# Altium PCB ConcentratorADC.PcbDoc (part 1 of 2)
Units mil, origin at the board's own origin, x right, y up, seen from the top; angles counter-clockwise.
Board outline 14400 x 5650 mil, 4 copper layers (Top Layer, Signal Layer 1, SG, Bottom Layer), stack 25.634 mil thick; 37 components, 129 nets, 1038 pads, 192 vias.
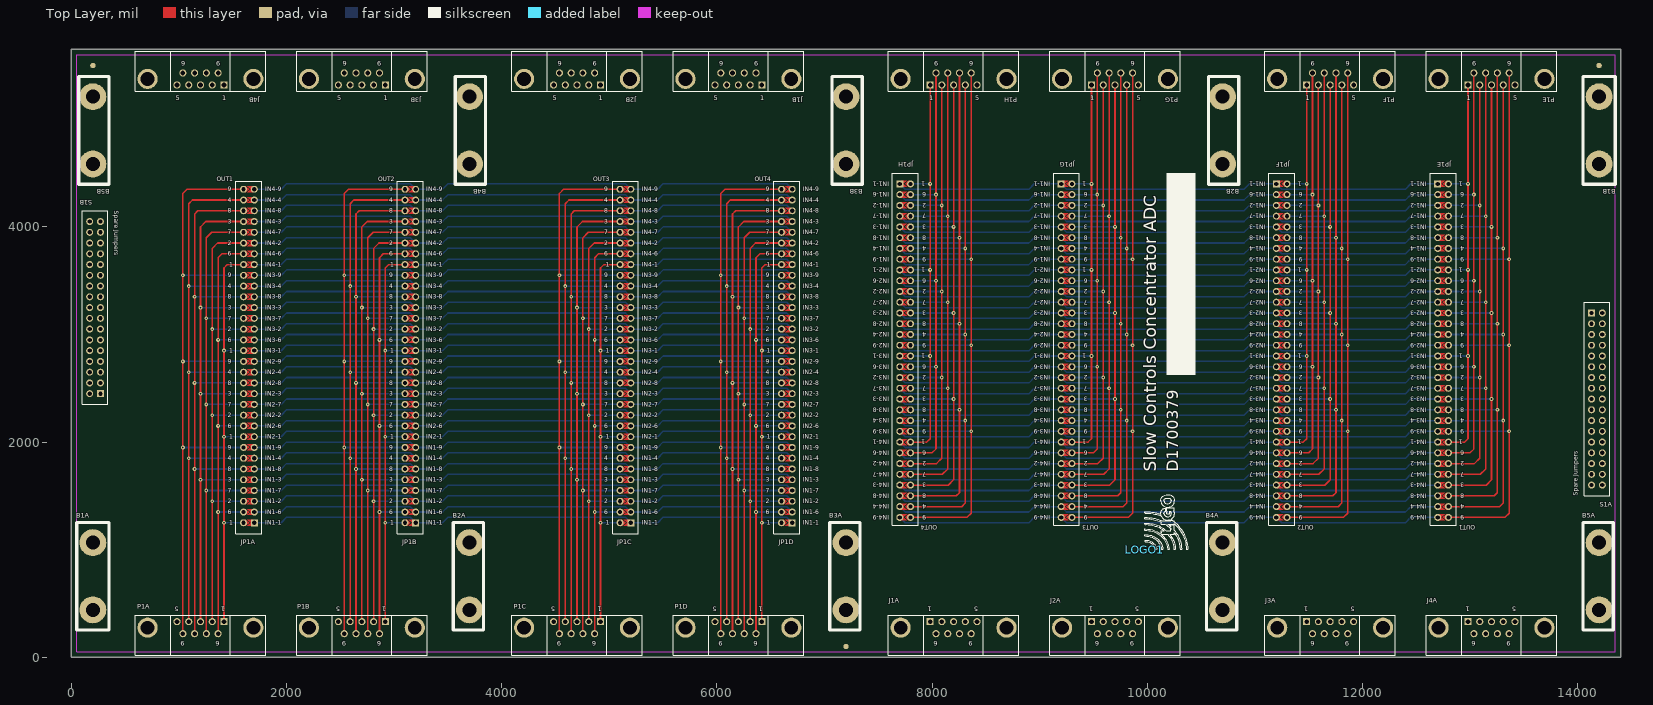
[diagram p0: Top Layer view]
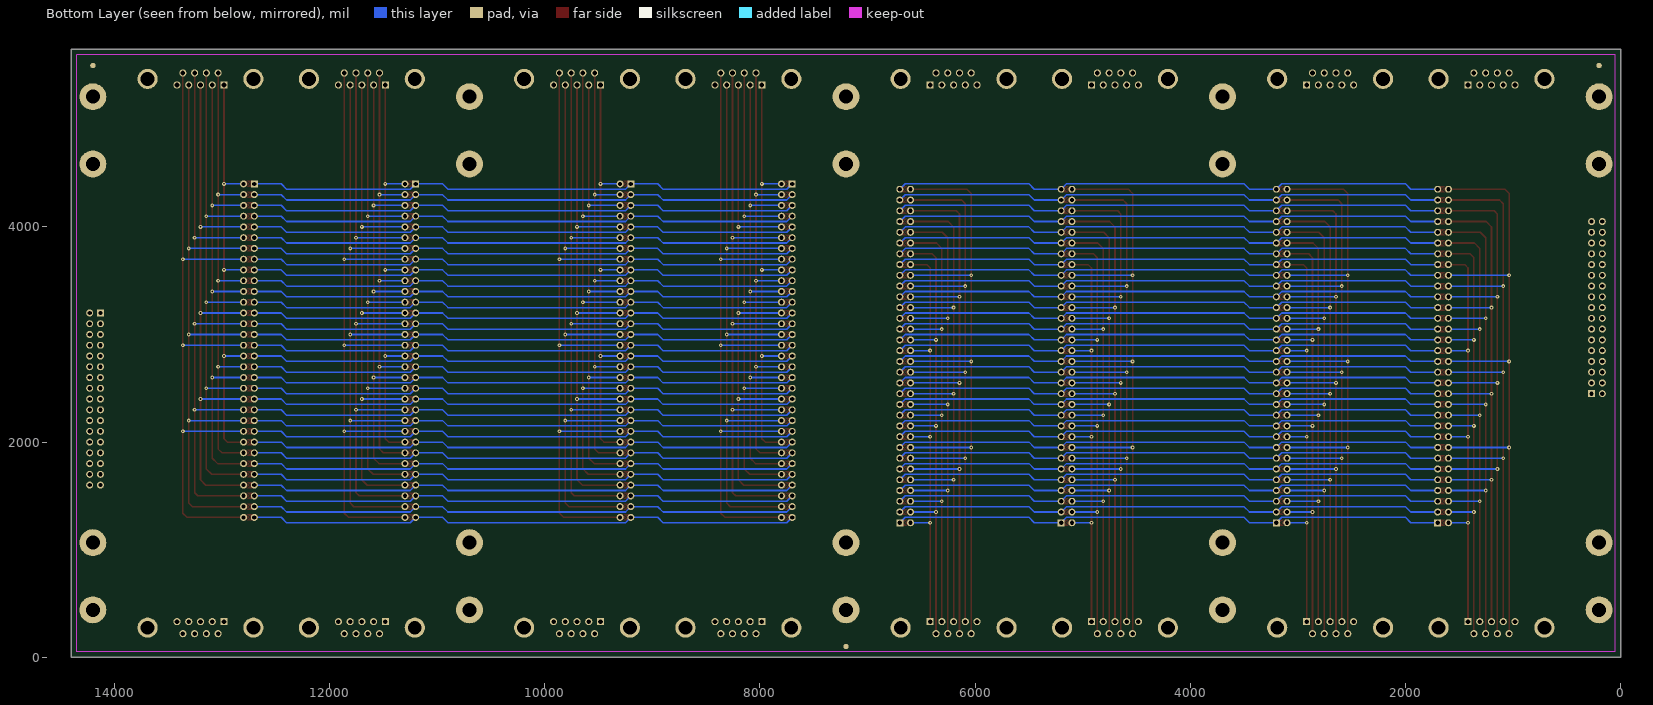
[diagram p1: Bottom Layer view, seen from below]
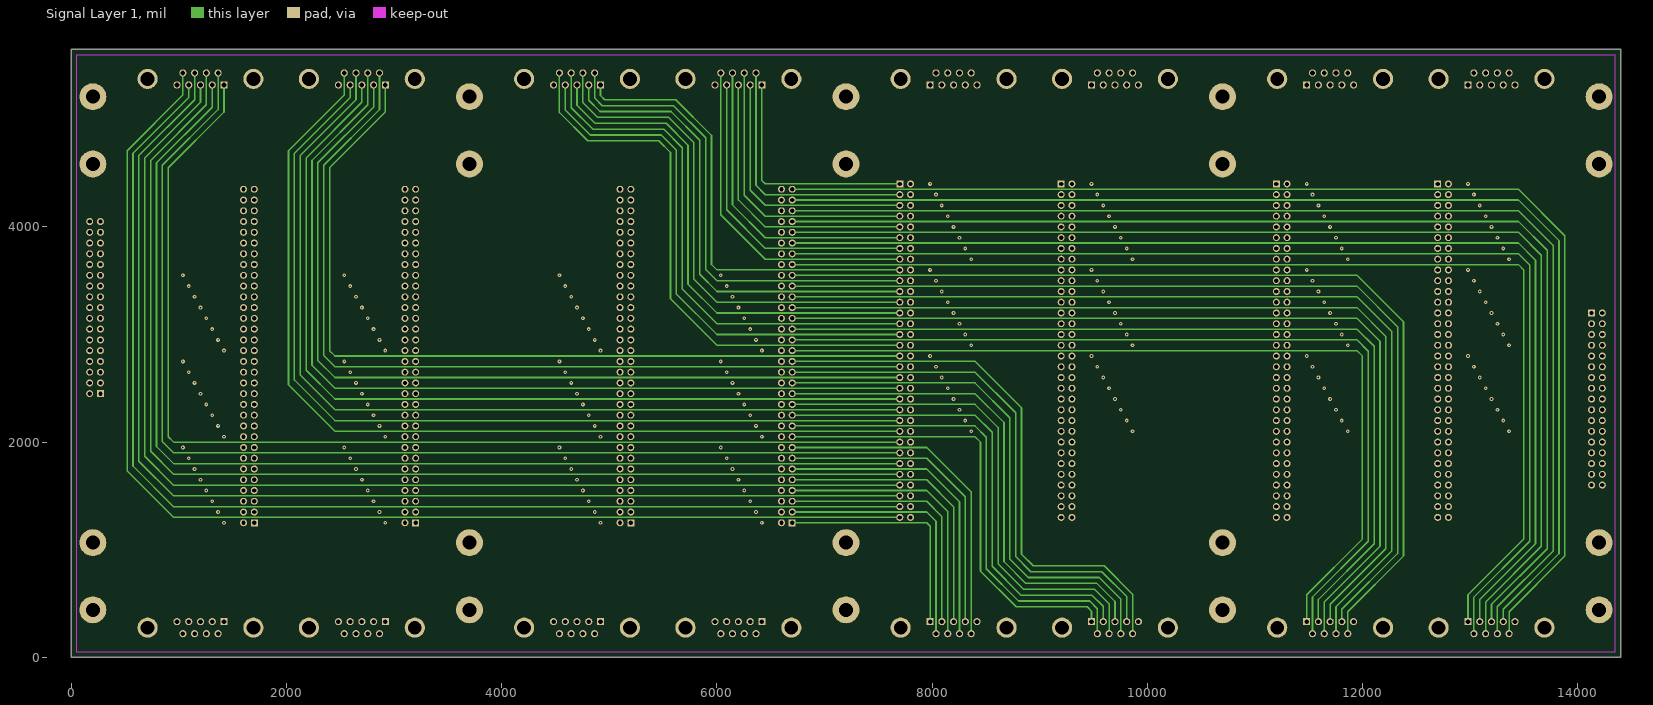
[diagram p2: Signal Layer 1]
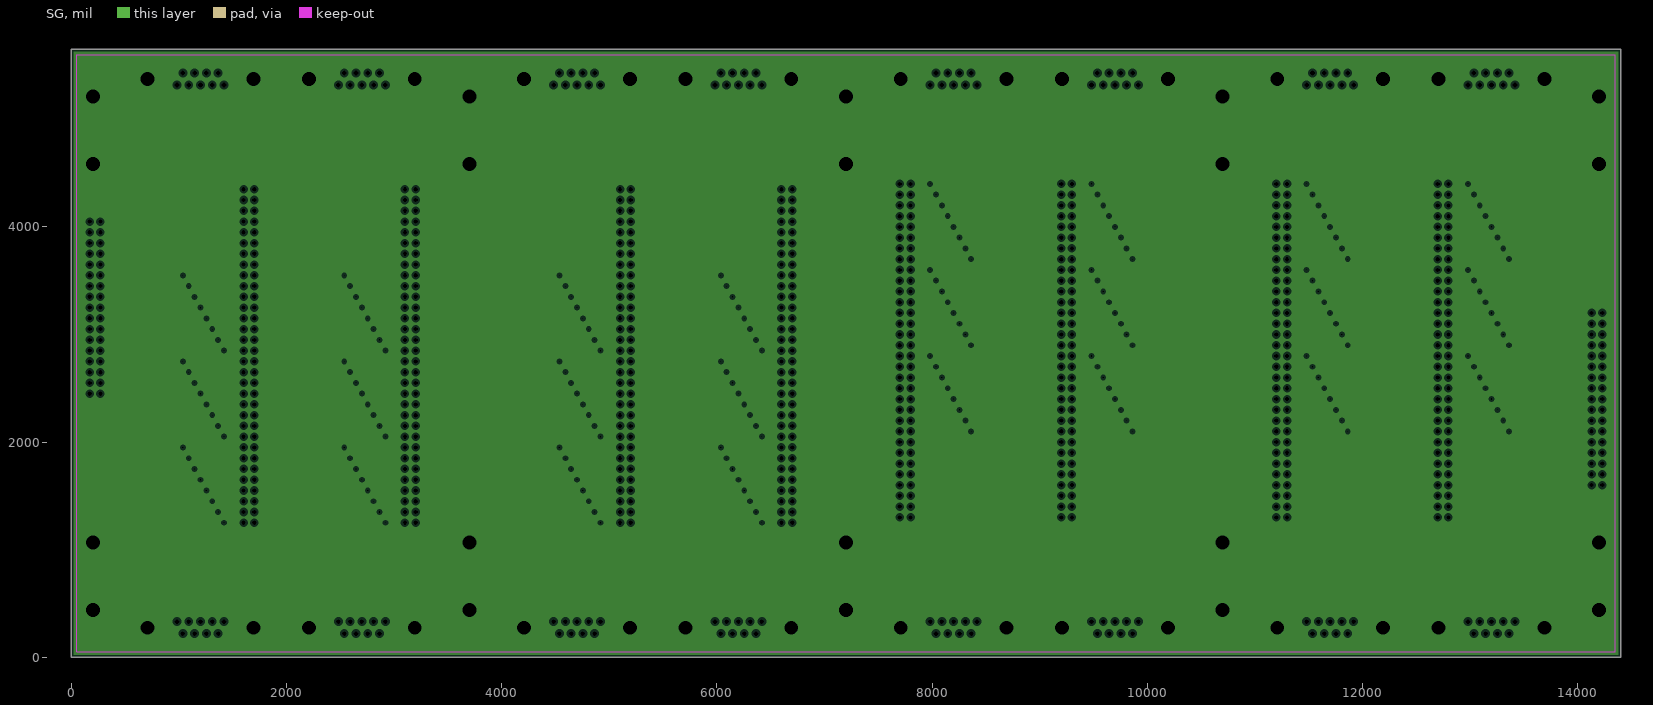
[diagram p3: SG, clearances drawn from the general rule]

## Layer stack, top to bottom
Top Solder: solder mask 0.4, Solder Resist, Dk 3.5
Top Layer: signal copper 1.4
Dielectric1: prepreg 5, FR-4, Dk 4.2
Signal Layer 1: signal copper 1.417
Dielectric 3: core 10, Dk 4.2
SG: plane copper 1.417, net SGA
Dielectric 2: prepreg 5, Dk 4.2
Bottom Layer: signal copper 1.4
Bottom Solder: solder mask 0.4, Solder Resist, Dk 3.5

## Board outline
0,0 14400,0 14400,5650 0,5650

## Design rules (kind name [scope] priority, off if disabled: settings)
Clearance [All] p1: gap=10 ignorepadtopadclearanceinfootprint=FALSE except(0: Arc-Hole Track-Hole SMDPad-Hole THPad-Hole Via-Hole Fill-Hole Poly-Hole Region-Hole Text-Hole)
FabricationTestPointUsage TestPointUsage [All] p1: valid=0 allowmultiple=FALSE
FabricationTestpoint Testpoint [All] p1: side=3 testpointundercomponent=TRUE minsize=40 maxsize=100 preferedsize=60 minholesize=0 maxholesize=40 preferedholesize=32 testpointgrid=1 allowsidetop=TRUE allowsidebottom=TRUE usegrid=TRUE gridtolerance=0.01
HoleSize [All] p1: absolutevalues=TRUE maxlimit=150 minlimit=15 maxpercent=80.000 minpercent=20.000
MinimumAnnularRing [All] p1: minimumring=10
PlaneClearance [All] p1: clearance=20
PlaneConnect [All] p1: planeconnectstyle=Relief reliefexpansion=20 reliefentries=4 reliefconductorwidth=10 reliefairgap=10
PolygonConnect [All] p1: connectstyle=Relief reliefconductorwidth=10 reliefentries=4 polygonreliefangle="90 Angle" airgapwidth=10
RoomDefinition OUT42 [InComponentClass('OUT42')] p1: confinementstyle=ConfineIn formatcopy=TRUE lockcomponents=FALSE outline 7400,1100 8900,1100 8900,6000 7400,6000
RoomDefinition OUT32 [InComponentClass('OUT32')] p2: confinementstyle=ConfineIn formatcopy=TRUE lockcomponents=FALSE outline 8900,1100 10400,1100 10400,6000 8900,6000
RoomDefinition OUT22 [InComponentClass('OUT22')] p3: confinementstyle=ConfineIn formatcopy=TRUE lockcomponents=FALSE outline 10900,1100 12400,1100 12400,6000 10900,6000
RoomDefinition OUT12 [InComponentClass('OUT12')] p4: confinementstyle=ConfineIn formatcopy=TRUE lockcomponents=FALSE outline 12400,1100 13900,1100 13900,6000 12400,6000
RoomDefinition OUT41 [InComponentClass('OUT41')] p5: confinementstyle=ConfineIn formatcopy=TRUE lockcomponents=FALSE outline 7000,4550 5500,4550 5500,-350 7000,-350
RoomDefinition OUT31 [InComponentClass('OUT31')] p6: confinementstyle=ConfineIn formatcopy=TRUE lockcomponents=FALSE outline 5500,4550 4000,4550 4000,-350 5500,-350
RoomDefinition OUT21 [InComponentClass('OUT21')] p7: confinementstyle=ConfineIn formatcopy=TRUE lockcomponents=FALSE outline 3500,4550 2000,4550 2000,-350 3500,-350
RoomDefinition OUT11 [InComponentClass('OUT11')] p8: confinementstyle=ConfineIn formatcopy=FALSE lockcomponents=FALSE outline 2000,4550 500,4550 500,-350 2000,-350
RoutingVias [All] p1: holewidth=15 width=35 viastyle="Through Hole" minholewidth=15 minwidth=15 maxholewidth=150 maxwidth=250
SilkToSolderMaskClearance SilkscreenOverComponentPads [IsPad] p1: minsilkscreentomaskgap=10 clearancetoexposedcopper=TRUE
SolderMaskExpansion [All] p1: expansion=4
Width [All] p1: maxlimit=100 minlimit=12 preferedwidth=12
24 further rules are at their usual default settings.

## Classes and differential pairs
channel class ConcentratorADC2: OUT1 OUT2 OUT3 OUT4
component class ConcentratorADC0: LOGO1
component class OUT11: JP1A JP1BA P1A
component class OUT12: JP1BE JP1E P1E
component class OUT21: JP1B JP1BB P1B
component class OUT22: JP1BF JP1F P1F
component class OUT31: JP1BC JP1C P1C
component class OUT32: JP1BG JP1G P1G
component class OUT41: JP1BD JP1D P1D
component class OUT42: JP1BH JP1H P1H
channel class ConcentratorADC1: Back Front

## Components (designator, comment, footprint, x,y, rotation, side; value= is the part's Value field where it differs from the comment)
B1A "Bracket" Bracket-RA_708 200,440 r0 top locked (schematic designator B1)
B1B "Bracket" Bracket-RA_708 14200,5210 r180 top locked (schematic designator B1)
B2A "Bracket" Bracket-RA_708 3700,440 r0 top locked (schematic designator B2)
B2B "Bracket" Bracket-RA_708 10700,5210 r180 top locked (schematic designator B2)
B3A "Bracket" Bracket-RA_708 7200,440 r0 top locked (schematic designator B3)
B3B "Bracket" Bracket-RA_708 7200,5210 r180 top locked (schematic designator B3)
B4A "Bracket" Bracket-RA_708 10700,440 r0 top locked (schematic designator B4)
B4B "Bracket" Bracket-RA_708 3700,5210 r180 top locked (schematic designator B4)
B5A "Bracket" Bracket-RA_708 14200,440 r0 top (schematic designator B5)
B5B "Bracket" Bracket-RA_708 200,5210 r180 top (schematic designator B5)
J1A "DB9M" DB9M-RA 8200,275 r180 top locked (schematic designator J1)
J1B "DB9M" DB9M-RA 6200,5375 r0 top locked (schematic designator J1)
J2A "DB9M" DB9M-RA 9700,275 r180 top locked (schematic designator J2)
J2B "DB9M" DB9M-RA 4700,5375 r0 top locked (schematic designator J2)
J3A "DB9M" DB9M-RA 11700,275 r180 top locked (schematic designator J3)
J3B "DB9M" DB9M-RA 2700,5375 r0 top locked (schematic designator J3)
J4A "DB9M" DB9M-RA 13200,275 r180 top locked (schematic designator J4)
J4B "DB9M" DB9M-RA 1200,5375 r0 top locked (schematic designator J4)
JP1A "09 18 164 9421" 9181649421 1650,2800 r90 top locked (schematic designator JP1)
JP1B "09 18 164 9421" 9181649421 3150,2800 r90 top locked (schematic designator JP1)
JP1C "09 18 164 9421" 9181649421 5150,2800 r90 top locked (schematic designator JP1)
JP1D "09 18 164 9421" 9181649421 6650,2800 r90 top locked (schematic designator JP1)
JP1E "09 18 164 9421" 9181649421 12750,2850 r270 top locked (schematic designator JP1)
JP1F "09 18 164 9421" 9181649421 11250,2850 r270 top locked (schematic designator JP1)
JP1G "09 18 164 9421" 9181649421 9250,2850 r270 top locked (schematic designator JP1)
JP1H "09 18 164 9421" 9181649421 7750,2850 r270 top locked (schematic designator JP1)
LOGO1 "LIGO logo" LIGO_LOGO 9975,1000 r90 top
P1A "DB9F" DB9F-RA 1200,275 r180 top locked (schematic designator P1)
P1B "DB9F" DB9F-RA 2700,275 r180 top locked (schematic designator P1)
P1C "DB9F" DB9F-RA 4700,275 r180 top locked (schematic designator P1)
P1D "DB9F" DB9F-RA 6200,275 r180 top locked (schematic designator P1)
P1E "DB9F" DB9F-RA 13200,5375 r0 top locked (schematic designator P1)
P1F "DB9F" DB9F-RA 11700,5375 r0 top locked (schematic designator P1)
P1G "DB9F" DB9F-RA 9700,5375 r0 top locked (schematic designator P1)
P1H "DB9F" DB9F-RA 8200,5375 r0 top locked (schematic designator P1)
S1A "Spare Jumpers" 9181349421 14179.92,2400 r270 top (schematic designator S1)
S1B "Spare Jumpers" 9181349421 220.08,3250 r90 top (schematic designator S1)

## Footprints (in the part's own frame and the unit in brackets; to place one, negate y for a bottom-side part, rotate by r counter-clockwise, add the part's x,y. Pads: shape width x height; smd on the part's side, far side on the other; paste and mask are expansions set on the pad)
9181349421 [mm] "Connector; IDC, PCB Transition - 2 Rows, Thru-Hole; 34 Position; Vertical; Pitch 2.54 mm; Body 48.48 x 6.1 x 7.45 mm (LxWxH), Kinked Contacts"
  rect 1.65x1.65 hole 1: 1(-20.32,-1.27)
  round 1.65 hole 1: 2(-20.32,1.27) 3(-17.78,-1.27) 4(-17.78,1.27) 5(-15.24,-1.27) 6(-15.24,1.27) 7(-12.7,-1.27) 8(-12.7,1.27) 9(-10.16,-1.27) 10(-10.16,1.27) 11(-7.62,-1.27) 12(-7.62,1.27) 13(-5.08,-1.27) 14(-5.08,1.27) 15(-2.54,-1.27) 16(-2.54,1.27) 17(0,-1.27) 18(0,1.27) 19(2.54,-1.27) 20(2.54,1.27) 21(5.08,-1.27) 22(5.08,1.27) 23(7.62,-1.27) 24(7.62,1.27) 25(10.16,-1.27) 26(10.16,1.27) 27(12.7,-1.27) 28(12.7,1.27) 29(15.24,-1.27) 30(15.24,1.27) 31(17.78,-1.27) 32(17.78,1.27) 33(20.32,-1.27) 34(20.32,1.27)
  silkscreen extent -22.86,-3.05 22.86,3.05
9181649421 [mm] "Connector; IDC, PCB Transition - 2 Rows, Thru-Hole; 64 Position; Vertical; Pitch 2.54 mm; Body 86.58 x 6.1 x 7.45 mm (LxWxH), Kinked Contacts"
  rect 1.65x1.65 hole 1: 1(-39.37,-1.27)
  round 1.65 hole 1: 2(-39.37,1.27) 3(-36.83,-1.27) 4(-36.83,1.27) 5(-34.29,-1.27) 6(-34.29,1.27) 7(-31.75,-1.27) 8(-31.75,1.27) 9(-29.21,-1.27) 10(-29.21,1.27) 11(-26.67,-1.27) 12(-26.67,1.27) 13(-24.13,-1.27) 14(-24.13,1.27) 15(-21.59,-1.27) 16(-21.59,1.27) 17(-19.05,-1.27) 18(-19.05,1.27) 19(-16.51,-1.27) 20(-16.51,1.27) 21(-13.97,-1.27) 22(-13.97,1.27) 23(-11.43,-1.27) 24(-11.43,1.27) 25(-8.89,-1.27) 26(-8.89,1.27) 27(-6.35,-1.27) 28(-6.35,1.27) 29(-3.81,-1.27) 30(-3.81,1.27) 31(-1.27,-1.27) 32(-1.27,1.27) 33(1.27,-1.27) 34(1.27,1.27) 35(3.81,-1.27) 36(3.81,1.27) 37(6.35,-1.27) 38(6.35,1.27) 39(8.89,-1.27) 40(8.89,1.27) 41(11.43,-1.27) 42(11.43,1.27) 43(13.97,-1.27) 44(13.97,1.27) 45(16.51,-1.27) 46(16.51,1.27) 47(19.05,-1.27) 48(19.05,1.27) 49(21.59,-1.27) 50(21.59,1.27) 51(24.13,-1.27) 52(24.13,1.27) 53(26.67,-1.27) 54(26.67,1.27) 55(29.21,-1.27) 56(29.21,1.27) 57(31.75,-1.27) 58(31.75,1.27) 59(34.29,-1.27) 60(34.29,1.27) 61(36.83,-1.27) 62(36.83,1.27) 63(39.37,-1.27) 64(39.37,1.27)
  silkscreen extent -41.91,-3.05 41.27,3.05
Bracket-RA_708 [mil] "Keystone Electronics right-angle 6-32 steel, 708"
  round 250 hole 130: 1(0,0) 2(0,625)
  silkscreen extent -150,-187 150,813
DB9F-RA [mm] "Receptiacle; D Subminiature 9 Position; Right Angle"
  rect 1.69x1.69 hole 1.09: 1(-5.54,-1.42)
  round 1.69 hole 1.09: 2(-2.77,-1.42) 3(0,-1.42) 4(2.77,-1.42) 5(5.54,-1.42) 6(-4.155,1.42) 7(-1.385,1.42) 8(1.385,1.42) 9(4.155,1.42)
  round 4.76 hole 3.26: 10(-12.495,0) 11(12.495,0)
  silkscreen extent -15.4,-2.9 15.4,6.5, body extent -15.49,-3.17 15.49,15.72, height 12.62
DB9M-RA [mm] "Plug; D Subminiature 9 Position; Right Angle"
  rect 1.69x1.69 hole 1.09: 1(5.54,-1.42)
  round 1.69 hole 1.09: 2(2.77,-1.42) 3(0,-1.42) 4(-2.77,-1.42) 5(-5.54,-1.42) 6(4.155,1.42) 7(1.385,1.42) 8(-1.385,1.42) 9(-4.155,1.42)
  round 4.76 hole 3.26: 10(12.495,0) 11(-12.495,0)
  silkscreen extent -15.4,-2.9 15.4,6.5, body extent -15.52,-3.24 15.52,15.37, height 12.62
LIGO_LOGO [mil] "LIGO logo"
  silkscreen extent 3,-402 511,-3

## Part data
B1A B1B B2A B2B B3A B3B B4A B4B B5A B5B: library part Bracket_708, "Keystone Electronics right-angle 6-32 steel, 708", Part Number=708K-ND
J1A J1B J2A J2B J3A J3B J4A J4B: "Plug Assembly, 9 Position, Right Angle, .318 Series", Part Number=A32094-ND
JP1A JP1B JP1C JP1D JP1E JP1F JP1G JP1H: "Flat Cable Connector (IDC), PCB Transition Connector, 2 Rows, Kinked Solder Pin, 64 Contacts", Part Number=609-3208-ND
LOGO1: library part LIGO_logo
P1A P1B P1C P1D P1E P1F P1G P1H: "Receptacle Assembly, 9 Position, Right Angle, .318 Series", Part Number=A32119-ND
S1A S1B: library part "09 18 134 9421", "Flat Cable Connector (IDC), PCB Transition Connector, 2 Rows, Kinked Solder Pin, 34 Contacts", Part Number=609-3208-ND

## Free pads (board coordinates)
  round 50 smd paste-50 mask+50: 0(200,5500) 0(7200,100) 0(14200,5500)
  round 50 smd far side paste-50 mask+50: 0(200,5500) 0(7200,100) 0(14200,5500)
  rect 0x0 smd paste-393.7 mask+31.5: 1(1650,1250) 1(1650,1350) 1(1650,1450) 1(1650,1550) 1(1650,1650) 1(1650,1750) 1(1650,1850) 1(1650,1950) 1(1650,2050) 1(1650,2250) 1(1650,2350) 1(1650,3350) 1(1650,3550) 1(1650,3750) 1(1650,3950) 1(1650,4050) 1(1651.25,2150) 1(1651.25,2450) 1(1651.25,2550) 1(1651.25,2650) 1(1651.25,2750) 1(1651.25,2850) 1(1651.25,2950) 1(1651.25,3050) 1(1651.25,3150) 1(1651.25,3250) 1(1651.25,3450) 1(1651.25,3650) 1(1651.25,3850) 1(1651.25,4150) 1(1651.25,4250) 1(1651.25,4350) 1(3150,1250) 1(3150,1350) 1(3150,1450) 1(3150,1550) 1(3150,1650) 1(3150,1750) 1(3150,1850) 1(3150,1950) 1(3150,2050) 1(3150,2250) 1(3150,2350) 1(3150,3350) 1(3150,3550) 1(3150,3750) 1(3150,3950) 1(3150,4050) 1(3151.25,2150) 1(3151.25,2450) 1(3151.25,2550) 1(3151.25,2650) 1(3151.25,2750) 1(3151.25,2850) 1(3151.25,2950) 1(3151.25,3050) 1(3151.25,3150) 1(3151.25,3250) 1(3151.25,3450) 1(3151.25,3650) 1(3151.25,3850) 1(3151.25,4150) 1(3151.25,4250) 1(3151.25,4350) 1(5150,1250) 1(5150,1350) 1(5150,1450) 1(5150,1550) 1(5150,1650) 1(5150,1750) 1(5150,1850) 1(5150,1950) 1(5150,2050) 1(5150,2250) 1(5150,2350) 1(5150,3350) 1(5150,3550) 1(5150,3750) 1(5150,3950) 1(5150,4050) 1(5151.25,2150) 1(5151.25,2450) 1(5151.25,2550) 1(5151.25,2650) 1(5151.25,2750) 1(5151.25,2850) 1(5151.25,2950) 1(5151.25,3050) 1(5151.25,3150) 1(5151.25,3250) 1(5151.25,3450) 1(5151.25,3650) 1(5151.25,3850) 1(5151.25,4150) 1(5151.25,4250) 1(5151.25,4350) 1(6650,1250) 1(6650,1350) 1(6650,1450) 1(6650,1550) 1(6650,1650) 1(6650,1750) 1(6650,1850) 1(6650,1950) 1(6650,2050) 1(6650,2250) 1(6650,2350) 1(6650,3350) 1(6650,3550) 1(6650,3750) 1(6650,3950) 1(6650,4050) 1(6651.25,2150) 1(6651.25,2450) 1(6651.25,2550) 1(6651.25,2650) 1(6651.25,2750) 1(6651.25,2850) 1(6651.25,2950) 1(6651.25,3050) 1(6651.25,3150) 1(6651.25,3250) 1(6651.25,3450) 1(6651.25,3650) 1(6651.25,3850) 1(6651.25,4150) 1(6651.25,4250) 1(6651.25,4350) 1(7748.75,1300) 1(7748.75,1400) 1(7748.75,1500) 1(7748.75,1800) 1(7748.75,2000) 1(7748.75,2200) 1(7748.75,2400) 1(7748.75,2500) 1(7748.75,2600) 1(7748.75,2700) 1(7748.75,2800) 1(7748.75,2900) 1(7748.75,3000) 1(7748.75,3100) 1(7748.75,3200) 1(7748.75,3500) 1(7750,1600) 1(7750,1700) 1(7750,1900) 1(7750,2100) 1(7750,2300) 1(7750,3300) 1(7750,3400) 1(7750,3600) 1(7750,3700) 1(7750,3800) 1(7750,3900) 1(7750,4000) 1(7750,4100) 1(7750,4200) 1(7750,4300) 1(7750,4400) 1(9248.75,1300) 1(9248.75,1400) 1(9248.75,1500) 1(9248.75,1800) 1(9248.75,2000) 1(9248.75,2200) 1(9248.75,2400) 1(9248.75,2500) 1(9248.75,2600) 1(9248.75,2700) 1(9248.75,2800) 1(9248.75,2900) 1(9248.75,3000) 1(9248.75,3100) 1(9248.75,3200) 1(9248.75,3500) 1(9250,1600) 1(9250,1700) 1(9250,1900) 1(9250,2100) 1(9250,2300) 1(9250,3300) 1(9250,3400) 1(9250,3600) 1(9250,3700) 1(9250,3800) 1(9250,3900) 1(9250,4000) 1(9250,4100) 1(9250,4200) 1(9250,4300) 1(9250,4400) 1(11248.75,1300) 1(11248.75,1400) 1(11248.75,1500) 1(11248.75,1800) 1(11248.75,2000) 1(11248.75,2200) 1(11248.75,2400) 1(11248.75,2500) 1(11248.75,2600) 1(11248.75,2700) 1(11248.75,2800) 1(11248.75,2900) 1(11248.75,3000) 1(11248.75,3100) 1(11248.75,3200) 1(11248.75,3500) 1(11250,1600) 1(11250,1700) 1(11250,1900) 1(11250,2100) 1(11250,2300) 1(11250,3300) 1(11250,3400) 1(11250,3600) 1(11250,3700) 1(11250,3800) 1(11250,3900) 1(11250,4000) 1(11250,4100) 1(11250,4200) 1(11250,4300) 1(11250,4400) 1(12748.75,1300) 1(12748.75,1400) 1(12748.75,1500) 1(12748.75,1800) 1(12748.75,2000) 1(12748.75,2200) 1(12748.75,2400) 1(12748.75,2500) 1(12748.75,2600) 1(12748.75,2700) 1(12748.75,2800) 1(12748.75,2900) 1(12748.75,3000) 1(12748.75,3100) 1(12748.75,3200) 1(12748.75,3500) 1(12750,1600) 1(12750,1700) 1(12750,1900) 1(12750,2100) 1(12750,2300) 1(12750,3300) 1(12750,3400) 1(12750,3600) 1(12750,3700) 1(12750,3800) 1(12750,3900) 1(12750,4000) 1(12750,4100) 1(12750,4200) 1(12750,4300) 1(12750,4400)

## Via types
v1: diameter 35, hole 15, Top Layer to Bottom Layer, 192 vias

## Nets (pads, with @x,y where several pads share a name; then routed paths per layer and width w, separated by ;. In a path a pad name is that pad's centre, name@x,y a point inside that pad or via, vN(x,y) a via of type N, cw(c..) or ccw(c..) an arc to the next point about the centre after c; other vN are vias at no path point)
NetJ1A_1: J1A.1 JP1A.1 JP1B.1 JP1C.1 JP1D.1 | length 7306.6
  Signal Layer 1 w15: JP1D.1@6700,1250 7950,1250 7981.89,1218.11 J1A.1@7981.89,330.91
  Bottom Layer w15: JP1A.1@1700,1250 1950,1250 2000,1300 3150,1300 JP1B.1@3200,1250 3450,1250 3500,1300 5150,1300 JP1C.1@5200,1250 5450,1250 5500,1300 6650,1300 JP1D.1@6700,1250
NetJ1A_2: J1A.2 JP1A.5 JP1B.5 JP1C.5 JP1D.5 | length 7551.7
  Signal Layer 1 w15: JP1D.5@6700,1450 7950,1450 8090.94,1309.06 J1A.2@8090.94,330.91
  Bottom Layer w15: JP1A.5@1700,1450 1950,1450 2000,1500 3150,1500 JP1B.5@3200,1450 3450,1450 3500,1500 5150,1500 JP1C.5@5200,1450 5450,1450 5500,1500 6650,1500 JP1D.5@6700,1450
NetJ1A_3: J1A.3 JP1A.9 JP1B.9 JP1C.9 JP1D.9 | length 7796.9
  Signal Layer 1 w15: JP1D.9@6700,1650 7950,1650 8200,1400 J1A.3@8200,330.91
  Bottom Layer w15: JP1A.9@1700,1650 1950,1650 2000,1700 3150,1700 JP1B.9@3200,1650 3450,1650 3500,1700 5150,1700 JP1C.9@5200,1650 5450,1650 5500,1700 6650,1700 JP1D.9@6700,1650
NetJ1A_4: J1A.4 JP1A.13 JP1B.13 JP1C.13 JP1D.13 | length 8042.1
  Signal Layer 1 w15: JP1D.13@6700,1850 7950,1850 8309.06,1490.94 J1A.4@8309.06,330.91
  Bottom Layer w15: JP1A.13@1700,1850 1950,1850 2000,1900 3150,1900 JP1B.13@3200,1850 3450,1850 3500,1900 5150,1900 JP1C.13@5200,1850 5450,1850 5500,1900 6650,1900 JP1D.13@6700,1850
NetJ1A_6: J1A.6 JP1A.3 JP1B.3 JP1C.3 JP1D.3 | length 7541
  Signal Layer 1 w15: JP1D.3@6700,1350 7950,1350 8036.42,1263.58 J1A.6@8036.42,219.09
  Bottom Layer w15: JP1A.3@1700,1350 1950,1350 2000,1400 3150,1400 JP1B.3@3200,1350 3450,1350 3500,1400 5150,1400 JP1C.3@5200,1350 5450,1350 5500,1400 6650,1400 JP1D.3@6700,1350
NetJ1A_7: J1A.7 JP1A.7 JP1B.7 JP1C.7 JP1D.7 | length 7786.1
  Signal Layer 1 w15: JP1D.7@6700,1550 7950,1550 8145.47,1354.53 J1A.7@8145.47,219.09
  Bottom Layer w15: JP1A.7@1700,1550 1950,1550 2000,1600 3150,1600 JP1B.7@3200,1550 3450,1550 3500,1600 5150,1600 JP1C.7@5200,1550 5450,1550 5500,1600 6650,1600 JP1D.7@6700,1550
NetJ1A_8: J1A.8 JP1A.11 JP1B.11 JP1C.11 JP1D.11 | length 8031.3
  Signal Layer 1 w15: JP1D.11@6700,1750 7950,1750 8254.53,1445.47 J1A.8@8254.53,219.09
  Bottom Layer w15: JP1A.11@1700,1750 1950,1750 2000,1800 3150,1800 JP1B.11@3200,1750 3450,1750 3500,1800 5150,1800 JP1C.11@5200,1750 5450,1750 5500,1800 6650,1800 JP1D.11@6700,1750
NetJ1A_9: J1A.9 JP1A.15 JP1B.15 JP1C.15 JP1D.15 | length 8276.5
  Signal Layer 1 w15: JP1D.15@6700,1950 7950,1950 8363.58,1536.42 J1A.9@8363.58,219.09
  Bottom Layer w15: JP1A.15@1700,1950 1950,1950 2000,2000 3150,2000 JP1B.15@3200,1950 3450,1950 3500,2000 5150,2000 JP1C.15@5200,1950 5450,1950 5500,2000 6650,2000 JP1D.15@6700,1950
NetJ1B_1: J1B.1 JP1E.1 JP1F.1 JP1G.1 JP1H.1 | length 7306.6
  Signal Layer 1 w15: J1B.1@6418.11,5319.09 6418.11,4431.89 6450,4400 JP1H.1@7700,4400
  Bottom Layer w15: JP1H.1@7700,4400 7750,4350 8900,4350 8950,4400 JP1G.1@9200,4400 9250,4350 10900,4350 10950,4400 JP1F.1@11200,4400 11250,4350 12400,4350 12450,4400 JP1E.1@12700,4400
NetJ1B_2: J1B.2 JP1E.5 JP1F.5 JP1G.5 JP1H.5 | length 7551.7
  Signal Layer 1 w15: J1B.2@6309.06,5319.09 6309.06,4340.94 6450,4200 JP1H.5@7700,4200
  Bottom Layer w15: JP1H.5@7700,4200 7750,4150 8900,4150 8950,4200 JP1G.5@9200,4200 9250,4150 10900,4150 10950,4200 JP1F.5@11200,4200 11250,4150 12400,4150 12450,4200 JP1E.5@12700,4200
NetJ1B_3: J1B.3 JP1E.9 JP1F.9 JP1G.9 JP1H.9 | length 7796.9
  Signal Layer 1 w15: J1B.3@6200,5319.09 6200,4250 6450,4000 JP1H.9@7700,4000
  Bottom Layer w15: JP1H.9@7700,4000 7750,3950 8900,3950 8950,4000 JP1G.9@9200,4000 9250,3950 10900,3950 10950,4000 JP1F.9@11200,4000 11250,3950 12400,3950 12450,4000 JP1E.9@12700,4000
NetJ1B_4: J1B.4 JP1E.13 JP1F.13 JP1G.13 JP1H.13 | length 8042.1
  Signal Layer 1 w15: J1B.4@6090.94,5319.09 6090.94,4159.06 6450,3800 JP1H.13@7700,3800
  Bottom Layer w15: JP1H.13@7700,3800 7750,3750 8900,3750 8950,3800 JP1G.13@9200,3800 9250,3750 10900,3750 10950,3800 JP1F.13@11200,3800 11250,3750 12400,3750 12450,3800 JP1E.13@12700,3800
NetJ1B_6: J1B.6 JP1E.3 JP1F.3 JP1G.3 JP1H.3 | length 7541
  Signal Layer 1 w15: J1B.6@6363.58,5430.91 6363.58,4386.42 6450,4300 JP1H.3@7700,4300
  Bottom Layer w15: JP1H.3@7700,4300 7750,4250 8900,4250 8950,4300 JP1G.3@9200,4300 9250,4250 10900,4250 10950,4300 JP1F.3@11200,4300 11250,4250 12400,4250 12450,4300 JP1E.3@12700,4300
NetJ1B_7: J1B.7 JP1E.7 JP1F.7 JP1G.7 JP1H.7 | length 7786.1
  Signal Layer 1 w15: J1B.7@6254.53,5430.91 6254.53,4295.47 6450,4100 JP1H.7@7700,4100
  Bottom Layer w15: JP1H.7@7700,4100 7750,4050 8900,4050 8950,4100 JP1G.7@9200,4100 9250,4050 10900,4050 10950,4100 JP1F.7@11200,4100 11250,4050 12400,4050 12450,4100 JP1E.7@12700,4100
NetJ1B_8: J1B.8 JP1E.11 JP1F.11 JP1G.11 JP1H.11 | length 8031.3
  Signal Layer 1 w15: J1B.8@6145.47,5430.91 6145.47,4204.53 6450,3900 JP1H.11@7700,3900
  Bottom Layer w15: JP1H.11@7700,3900 7750,3850 8900,3850 8950,3900 JP1G.11@9200,3900 9250,3850 10900,3850 10950,3900 JP1F.11@11200,3900 11250,3850 12400,3850 12450,3900 JP1E.11@12700,3900
NetJ1B_9: J1B.9 JP1E.15 JP1F.15 JP1G.15 JP1H.15 | length 8276.5
  Signal Layer 1 w15: J1B.9@6036.42,5430.91 6036.42,4113.58 6450,3700 JP1H.15@7700,3700
  Bottom Layer w15: JP1H.15@7700,3700 7750,3650 8900,3650 8950,3700 JP1G.15@9200,3700 9250,3650 10900,3650 10950,3700 JP1F.15@11200,3700 11250,3650 12400,3650 12450,3700 JP1E.15@12700,3700
NetJ2A_1: J2A.1 JP1A.17 JP1B.17 JP1C.17 JP1D.17 | length 9378.2
  Signal Layer 1 w15: JP1D.17@6700,2050 8400,2050 8450,2000 8450,800 8781.69,468.31 9441.9,468.31 9481.89,428.32 J2A.1@9481.89,330.91
  Bottom Layer w15: JP1A.17@1700,2050 1950,2050 2000,2100 3150,2100 JP1B.17@3200,2050 3450,2050 3500,2100 5150,2100 JP1C.17@5200,2050 5450,2050 5500,2100 6650,2100 JP1D.17@6700,2050
NetJ2A_2: J2A.2 JP1A.21 JP1B.21 JP1C.21 JP1D.21 | length 9623.4
  Signal Layer 1 w15: JP1D.21@6700,2250 8400,2250 8559.06,2090.94 8559.06,845.17 8826.86,577.36 9487.07,577.36 9590.94,473.49 J2A.2@9590.94,330.91
  Bottom Layer w15: JP1A.21@1700,2250 1950,2250 2000,2300 3150,2300 JP1B.21@3200,2250 3450,2250 3500,2300 5150,2300 JP1C.21@5200,2250 5450,2250 5500,2300 6650,2300 JP1D.21@6700,2250
NetJ2A_3: J2A.3 JP1A.25 JP1B.25 JP1C.25 JP1D.25 | length 9868.6
  Signal Layer 1 w15: JP1D.25@6700,2450 8400,2450 8668.11,2181.89 8668.11,890.34 8872.04,686.42 9532.24,686.42 9700,518.66 J2A.3@9700,330.91
  Bottom Layer w15: JP1A.25@1700,2450 1950,2450 2000,2500 3150,2500 JP1B.25@3200,2450 3450,2450 3500,2500 5150,2500 JP1C.25@5200,2450 5450,2450 5500,2500 6650,2500 JP1D.25@6700,2450
NetJ2A_4: J2A.4 JP1A.29 JP1B.29 JP1C.29 JP1D.29 | length 10113.7
  Signal Layer 1 w15: JP1D.29@6700,2650 8400,2650 8777.17,2272.83 8777.17,935.52 8917.21,795.47 9577.41,795.47 9809.06,563.83 J2A.4@9809.06,330.91
  Bottom Layer w15: JP1A.29@1700,2650 1950,2650 2000,2700 3150,2700 JP1B.29@3200,2650 3450,2650 3500,2700 5150,2700 JP1C.29@5200,2650 5450,2650 5500,2700 6650,2700 JP1D.29@6700,2650
NetJ2A_6: J2A.6 JP1A.19 JP1B.19 JP1C.19 JP1D.19 | length 9612.6
  Signal Layer 1 w15: JP1D.19@6700,2150 8400,2150 8504.53,2045.47 8504.53,822.59 8804.28,522.83 9464.48,522.83 9536.42,450.9 J2A.6@9536.42,219.09
  Bottom Layer w15: JP1A.19@1700,2150 1950,2150 2000,2200 3150,2200 JP1B.19@3200,2150 3450,2150 3500,2200 5150,2200 JP1C.19@5200,2150 5450,2150 5500,2200 6650,2200 JP1D.19@6700,2150
NetJ2A_7: J2A.7 JP1A.23 JP1B.23 JP1C.23 JP1D.23 | length 9857.8
  Signal Layer 1 w15: JP1D.23@6700,2350 8400,2350 8613.58,2136.42 8613.58,867.76 8849.45,631.89 9509.66,631.89 9645.47,496.07 J2A.7@9645.47,219.09
  Bottom Layer w15: JP1A.23@1700,2350 1950,2350 2000,2400 3150,2400 JP1B.23@3200,2350 3450,2350 3500,2400 5150,2400 JP1C.23@5200,2350 5450,2350 5500,2400 6650,2400 JP1D.23@6700,2350
NetJ2A_8: J2A.8 JP1A.27 JP1B.27 JP1C.27 JP1D.27 | length 10103
  Signal Layer 1 w15: JP1D.27@6700,2550 8400,2550 8722.64,2227.36 8722.64,912.93 8894.62,740.94 9554.83,740.94 9754.53,541.25 J2A.8@9754.53,219.09
  Bottom Layer w15: JP1A.27@1700,2550 1950,2550 2000,2600 3150,2600 JP1B.27@3200,2550 3450,2550 3500,2600 5150,2600 JP1C.27@5200,2550 5450,2550 5500,2600 6650,2600 JP1D.27@6700,2550
NetJ2A_9: J2A.9 JP1A.31 JP1B.31 JP1C.31 JP1D.31 | length 10348.1
  Signal Layer 1 w15: JP1D.31@6700,2750 8400,2750 8831.69,2318.31 8831.69,958.1 8939.8,850 9600,850 9863.58,586.42 J2A.9@9863.58,219.09
  Bottom Layer w15: JP1A.31@1700,2750 1950,2750 2000,2800 3150,2800 JP1B.31@3200,2750 3450,2750 3500,2800 5150,2800 JP1C.31@5200,2750 5450,2750 5500,2800 6650,2800 JP1D.31@6700,2750
NetJ2B_1: J2B.1 JP1E.17 JP1F.17 JP1G.17 JP1H.17 | length 9378.2
  Signal Layer 1 w15: J2B.1@4918.11,5319.09 4918.11,5221.68 4958.1,5181.69 5618.31,5181.69 5950,4850 5950,3650 6000,3600 JP1H.17@7700,3600
  Bottom Layer w15: JP1H.17@7700,3600 7750,3550 8900,3550 8950,3600 JP1G.17@9200,3600 9250,3550 10900,3550 10950,3600 JP1F.17@11200,3600 11250,3550 12400,3550 12450,3600 JP1E.17@12700,3600
NetJ2B_2: J2B.2 JP1E.21 JP1F.21 JP1G.21 JP1H.21 | length 9623.4
  Signal Layer 1 w15: J2B.2@4809.06,5319.09 4809.06,5176.51 4912.93,5072.64 5573.14,5072.64 5840.94,4804.83 5840.94,3559.06 6000,3400 JP1H.21@7700,3400
  Bottom Layer w15: JP1H.21@7700,3400 7750,3350 8900,3350 8950,3400 JP1G.21@9200,3400 9250,3350 10900,3350 10950,3400 JP1F.21@11200,3400 11250,3350 12400,3350 12450,3400 JP1E.21@12700,3400
NetJ2B_3: J2B.3 JP1E.25 JP1F.25 JP1G.25 JP1H.25 | length 9868.6
  Signal Layer 1 w15: J2B.3@4700,5319.09 4700,5131.34 4867.76,4963.58 5527.96,4963.58 5731.89,4759.66 5731.89,3468.11 6000,3200 JP1H.25@7700,3200
  Bottom Layer w15: JP1H.25@7700,3200 7750,3150 8900,3150 8950,3200 JP1G.25@9200,3200 9250,3150 10900,3150 10950,3200 JP1F.25@11200,3200 11250,3150 12400,3150 12450,3200 JP1E.25@12700,3200
NetJ2B_4: J2B.4 JP1E.29 JP1F.29 JP1G.29 JP1H.29 | length 10113.7
  Signal Layer 1 w15: J2B.4@4590.94,5319.09 4590.94,5086.17 4822.59,4854.53 5482.79,4854.53 5622.83,4714.48 5622.83,3377.17 6000,3000 JP1H.29@7700,3000
  Bottom Layer w15: JP1H.29@7700,3000 7750,2950 8900,2950 8950,3000 JP1G.29@9200,3000 9250,2950 10900,2950 10950,3000 JP1F.29@11200,3000 11250,2950 12400,2950 12450,3000 JP1E.29@12700,3000
NetJ2B_6: J2B.6 JP1E.19 JP1F.19 JP1G.19 JP1H.19 | length 9612.6
  Signal Layer 1 w15: J2B.6@4863.58,5430.91 4863.58,5199.1 4935.52,5127.17 5595.72,5127.17 5895.47,4827.41 5895.47,3604.53 6000,3500 JP1H.19@7700,3500
  Bottom Layer w15: JP1H.19@7700,3500 7750,3450 8900,3450 8950,3500 JP1G.19@9200,3500 9250,3450 10900,3450 10950,3500 JP1F.19@11200,3500 11250,3450 12400,3450 12450,3500 JP1E.19@12700,3500
NetJ2B_7: J2B.7 JP1E.23 JP1F.23 JP1G.23 JP1H.23 | length 9857.8
  Signal Layer 1 w15: J2B.7@4754.53,5430.91 4754.53,5153.93 4890.34,5018.11 5550.55,5018.11 5786.42,4782.24 5786.42,3513.58 6000,3300 JP1H.23@7700,3300
  Bottom Layer w15: JP1H.23@7700,3300 7750,3250 8900,3250 8950,3300 JP1G.23@9200,3300 9250,3250 10900,3250 10950,3300 JP1F.23@11200,3300 11250,3250 12400,3250 12450,3300 JP1E.23@12700,3300
NetJ2B_8: J2B.8 JP1E.27 JP1F.27 JP1G.27 JP1H.27 | length 10103
  Signal Layer 1 w15: J2B.8@4645.47,5430.91 4645.47,5108.75 4845.17,4909.06 5505.38,4909.06 5677.36,4737.07 5677.36,3422.64 6000,3100 JP1H.27@7700,3100
  Bottom Layer w15: JP1H.27@7700,3100 7750,3050 8900,3050 8950,3100 JP1G.27@9200,3100 9250,3050 10900,3050 10950,3100 JP1F.27@11200,3100 11250,3050 12400,3050 12450,3100 JP1E.27@12700,3100
NetJ2B_9: J2B.9 JP1E.31 JP1F.31 JP1G.31 JP1H.31 | length 10348.1
  Signal Layer 1 w15: J2B.9@4536.42,5430.91 4536.42,5063.58 4800,4800 5460.2,4800 5568.31,4691.9 5568.31,3331.69 6000,2900 JP1H.31@7700,2900
  Bottom Layer w15: JP1H.31@7700,2900 7750,2850 8900,2850 8950,2900 JP1G.31@9200,2900 9250,2850 10900,2850 10950,2900 JP1F.31@11200,2900 11250,2850 12400,2850 12450,2900 JP1E.31@12700,2900
NetJ3A_1: J3A.1 JP1A.33 JP1B.33 JP1C.33 JP1D.33 | length 13128.7
  Signal Layer 1 w15: JP1D.33@6700,2850 11950,2850 12000,2800 12000,1100 11481.89,581.89 J3A.1@11481.89,330.91
  Bottom Layer w15: JP1A.33@1700,2850 1950,2850 2000,2900 3150,2900 JP1B.33@3200,2850 3450,2850 3500,2900 5150,2900 JP1C.33@5200,2850 5450,2850 5500,2900 6650,2900 JP1D.33@6700,2850
NetJ3A_2: J3A.2 JP1A.37 JP1B.37 JP1C.37 JP1D.37 | length 13373.9
  Signal Layer 1 w15: JP1D.37@6700,3050 11950,3050 12109.06,2890.94 12109.06,1054.83 11590.94,536.72 J3A.2@11590.94,330.91
  Bottom Layer w15: JP1A.37@1700,3050 1950,3050 2000,3100 3150,3100 JP1B.37@3200,3050 3450,3050 3500,3100 5150,3100 JP1C.37@5200,3050 5450,3050 5500,3100 6650,3100 JP1D.37@6700,3050
NetJ3A_3: J3A.3 JP1A.41 JP1B.41 JP1C.41 JP1D.41 | length 13619
  Signal Layer 1 w15: JP1D.41@6700,3250 11950,3250 12218.11,2981.89 12218.11,1009.66 11700,491.55 J3A.3@11700,330.91
  Bottom Layer w15: JP1A.41@1700,3250 1950,3250 2000,3300 3150,3300 JP1B.41@3200,3250 3450,3250 3500,3300 5150,3300 JP1C.41@5200,3250 5450,3250 5500,3300 6650,3300 JP1D.41@6700,3250
NetJ3A_4: J3A.4 JP1A.45 JP1B.45 JP1C.45 JP1D.45 | length 13864.2
  Signal Layer 1 w15: JP1D.45@6700,3450 11950,3450 12327.17,3072.83 12327.17,964.48 11809.06,446.37 J3A.4@11809.06,330.91
  Bottom Layer w15: JP1A.45@1700,3450 1950,3450 2000,3500 3150,3500 JP1B.45@3200,3450 3450,3450 3500,3500 5150,3500 JP1C.45@5200,3450 5450,3450 5500,3500 6650,3500 JP1D.45@6700,3450
NetJ3A_6: J3A.6 JP1A.35 JP1B.35 JP1C.35 JP1D.35 | length 13363.1
  Signal Layer 1 w15: JP1D.35@6700,2950 11950,2950 12054.53,2845.47 12054.53,1077.41 11536.42,559.3 J3A.6@11536.42,219.09
  Bottom Layer w15: JP1A.35@1700,2950 1950,2950 2000,3000 3150,3000 JP1B.35@3200,2950 3450,2950 3500,3000 5150,3000 JP1C.35@5200,2950 5450,2950 5500,3000 6650,3000 JP1D.35@6700,2950
NetJ3A_7: J3A.7 JP1A.39 JP1B.39 JP1C.39 JP1D.39 | length 13608.2
  Signal Layer 1 w15: JP1D.39@6700,3150 11950,3150 12163.58,2936.42 12163.58,1032.24 11645.47,514.13 J3A.7@11645.47,219.09
  Bottom Layer w15: JP1A.39@1700,3150 1950,3150 2000,3200 3150,3200 JP1B.39@3200,3150 3450,3150 3500,3200 5150,3200 JP1C.39@5200,3150 5450,3150 5500,3200 6650,3200 JP1D.39@6700,3150
NetJ3A_8: J3A.8 JP1A.43 JP1B.43 JP1C.43 JP1D.43 | length 13853.4
  Signal Layer 1 w15: JP1D.43@6700,3350 11950,3350 12272.64,3027.36 12272.64,987.07 11754.53,468.96 J3A.8@11754.53,219.09
  Bottom Layer w15: JP1A.43@1700,3350 1950,3350 2000,3400 3150,3400 JP1B.43@3200,3350 3450,3350 3500,3400 5150,3400 JP1C.43@5200,3350 5450,3350 5500,3400 6650,3400 JP1D.43@6700,3350
NetJ3A_9: J3A.9 JP1A.47 JP1B.47 JP1C.47 JP1D.47 | length 14098.6
  Signal Layer 1 w15: JP1D.47@6700,3550 11950,3550 12381.69,3118.31 12381.69,941.9 11863.58,423.79 J3A.9@11863.58,219.09
  Bottom Layer w15: JP1A.47@1700,3550 1950,3550 2000,3600 3150,3600 JP1B.47@3200,3550 3450,3550 3500,3600 5150,3600 JP1C.47@5200,3550 5450,3550 5500,3600 6650,3600 JP1D.47@6700,3550
NetJ3B_1: J3B.1 JP1E.33 JP1F.33 JP1G.33 JP1H.33 | length 13128.7
  Signal Layer 1 w15: J3B.1@2918.11,5319.09 2918.11,5068.11 2400,4550 2400,2850 2450,2800 JP1H.33@7700,2800
  Bottom Layer w15: JP1H.33@7700,2800 7750,2750 8900,2750 8950,2800 JP1G.33@9200,2800 9250,2750 10900,2750 10950,2800 JP1F.33@11200,2800 11250,2750 12400,2750 12450,2800 JP1E.33@12700,2800
NetJ3B_2: J3B.2 JP1E.37 JP1F.37 JP1G.37 JP1H.37 | length 13373.9
  Signal Layer 1 w15: J3B.2@2809.06,5319.09 2809.06,5113.28 2290.94,4595.17 2290.94,2759.06 2450,2600 JP1H.37@7700,2600
  Bottom Layer w15: JP1H.37@7700,2600 7750,2550 8900,2550 8950,2600 JP1G.37@9200,2600 9250,2550 10900,2550 10950,2600 JP1F.37@11200,2600 11250,2550 12400,2550 12450,2600 JP1E.37@12700,2600
NetJ3B_3: J3B.3 JP1E.41 JP1F.41 JP1G.41 JP1H.41 | length 13619
  Signal Layer 1 w15: J3B.3@2700,5319.09 2700,5158.45 2181.89,4640.34 2181.89,2668.11 2450,2400 JP1H.41@7700,2400
  Bottom Layer w15: JP1H.41@7700,2400 7750,2350 8900,2350 8950,2400 JP1G.41@9200,2400 9250,2350 10900,2350 10950,2400 JP1F.41@11200,2400 11250,2350 12400,2350 12450,2400 JP1E.41@12700,2400
NetJ3B_4: J3B.4 JP1E.45 JP1F.45 JP1G.45 JP1H.45 | length 13864.2
  Signal Layer 1 w15: J3B.4@2590.94,5319.09 2590.94,5203.63 2072.83,4685.52 2072.83,2577.17 2450,2200 JP1H.45@7700,2200
  Bottom Layer w15: JP1H.45@7700,2200 7750,2150 8900,2150 8950,2200 JP1G.45@9200,2200 9250,2150 10900,2150 10950,2200 JP1F.45@11200,2200 11250,2150 12400,2150 12450,2200 JP1E.45@12700,2200
NetJ3B_6: J3B.6 JP1E.35 JP1F.35 JP1G.35 JP1H.35 | length 13363.1
  Signal Layer 1 w15: J3B.6@2863.58,5430.91 2863.58,5090.7 2345.47,4572.59 2345.47,2804.53 2450,2700 JP1H.35@7700,2700
  Bottom Layer w15: JP1H.35@7700,2700 7750,2650 8900,2650 8950,2700 JP1G.35@9200,2700 9250,2650 10900,2650 10950,2700 JP1F.35@11200,2700 11250,2650 12400,2650 12450,2700 JP1E.35@12700,2700
NetJ3B_7: J3B.7 JP1E.39 JP1F.39 JP1G.39 JP1H.39 | length 13608.2
  Signal Layer 1 w15: J3B.7@2754.53,5430.91 2754.53,5135.87 2236.42,4617.76 2236.42,2713.58 2450,2500 JP1H.39@7700,2500
  Bottom Layer w15: JP1H.39@7700,2500 7750,2450 8900,2450 8950,2500 JP1G.39@9200,2500 9250,2450 10900,2450 10950,2500 JP1F.39@11200,2500 11250,2450 12400,2450 12450,2500 JP1E.39@12700,2500
NetJ3B_8: J3B.8 JP1E.43 JP1F.43 JP1G.43 JP1H.43 | length 13853.4
  Signal Layer 1 w15: J3B.8@2645.47,5430.91 2645.47,5181.04 2127.36,4662.93 2127.36,2622.64 2450,2300 JP1H.43@7700,2300
  Bottom Layer w15: JP1H.43@7700,2300 7750,2250 8900,2250 8950,2300 JP1G.43@9200,2300 9250,2250 10900,2250 10950,2300 JP1F.43@11200,2300 11250,2250 12400,2250 12450,2300 JP1E.43@12700,2300
NetJ3B_9: J3B.9 JP1E.47 JP1F.47 JP1G.47 JP1H.47 | length 14098.6
  Signal Layer 1 w15: J3B.9@2536.42,5430.91 2536.42,5226.21 2018.31,4708.1 2018.31,2531.69 2450,2100 JP1H.47@7700,2100
  Bottom Layer w15: JP1H.47@7700,2100 7750,2050 8900,2050 8950,2100 JP1G.47@9200,2100 9250,2050 10900,2050 10950,2100 JP1F.47@11200,2100 11250,2050 12400,2050 12450,2100 JP1E.47@12700,2100
NetJ4A_1: J4A.1 JP1A.49 JP1B.49 JP1C.49 JP1D.49 | length 15428.7
  Signal Layer 1 w15: JP1D.49@6700,3650 13450,3650 13500,3600 13500,1100 12981.89,581.89 J4A.1@12981.89,330.91
  Bottom Layer w15: JP1A.49@1700,3650 1950,3650 2000,3700 3150,3700 JP1B.49@3200,3650 3450,3650 3500,3700 5150,3700 JP1C.49@5200,3650 5450,3650 5500,3700 6650,3700 JP1D.49@6700,3650
NetJ4A_2: J4A.2 JP1A.53 JP1B.53 JP1C.53 JP1D.53 | length 15673.9
  Signal Layer 1 w15: JP1D.53@6700,3850 13450,3850 13609.06,3690.94 13609.06,1054.83 13090.94,536.72 J4A.2@13090.94,330.91
  Bottom Layer w15: JP1A.53@1700,3850 1950,3850 2000,3900 3150,3900 JP1B.53@3200,3850 3450,3850 3500,3900 5150,3900 JP1C.53@5200,3850 5450,3850 5500,3900 6650,3900 JP1D.53@6700,3850
NetJ4A_3: J4A.3 JP1A.57 JP1B.57 JP1C.57 JP1D.57 | length 15919
  Signal Layer 1 w15: JP1D.57@6700,4050 13450,4050 13718.11,3781.89 13718.11,1009.66 13200,491.55 J4A.3@13200,330.91
  Bottom Layer w15: JP1A.57@1700,4050 1950,4050 2000,4100 3150,4100 JP1B.57@3200,4050 3450,4050 3500,4100 5150,4100 JP1C.57@5200,4050 5450,4050 5500,4100 6650,4100 JP1D.57@6700,4050
NetJ4A_4: J4A.4 JP1A.61 JP1B.61 JP1C.61 JP1D.61 | length 16164.2
  Signal Layer 1 w15: JP1D.61@6700,4250 13450,4250 13827.17,3872.83 13827.17,964.48 13309.06,446.37 J4A.4@13309.06,330.91
  Bottom Layer w15: JP1A.61@1700,4250 1950,4250 2000,4300 3150,4300 JP1B.61@3200,4250 3450,4250 3500,4300 5150,4300 JP1C.61@5200,4250 5450,4250 5500,4300 6650,4300 JP1D.61@6700,4250
NetJ4A_6: J4A.6 JP1A.51 JP1B.51 JP1C.51 JP1D.51 | length 15663.1
  Signal Layer 1 w15: JP1D.51@6700,3750 13450,3750 13554.53,3645.47 13554.53,1077.41 13036.42,559.3 J4A.6@13036.42,219.09
  Bottom Layer w15: JP1A.51@1700,3750 1950,3750 2000,3800 3150,3800 JP1B.51@3200,3750 3450,3750 3500,3800 5150,3800 JP1C.51@5200,3750 5450,3750 5500,3800 6650,3800 JP1D.51@6700,3750
NetJ4A_7: J4A.7 JP1A.55 JP1B.55 JP1C.55 JP1D.55 | length 15908.2
  Signal Layer 1 w15: JP1D.55@6700,3950 13450,3950 13663.58,3736.42 13663.58,1032.24 13145.47,514.13 J4A.7@13145.47,219.09
  Bottom Layer w15: JP1A.55@1700,3950 1950,3950 2000,4000 3150,4000 JP1B.55@3200,3950 3450,3950 3500,4000 5150,4000 JP1C.55@5200,3950 5450,3950 5500,4000 6650,4000 JP1D.55@6700,3950
NetJ4A_8: J4A.8 JP1A.59 JP1B.59 JP1C.59 JP1D.59 | length 16153.4
  Signal Layer 1 w15: JP1D.59@6700,4150 13450,4150 13772.64,3827.36 13772.64,987.07 13254.53,468.96 J4A.8@13254.53,219.09
  Bottom Layer w15: JP1A.59@1700,4150 1950,4150 2000,4200 3150,4200 JP1B.59@3200,4150 3450,4150 3500,4200 5150,4200 JP1C.59@5200,4150 5450,4150 5500,4200 6650,4200 JP1D.59@6700,4150
NetJ4A_9: J4A.9 JP1A.63 JP1B.63 JP1C.63 JP1D.63 | length 16398.6
  Signal Layer 1 w15: JP1D.63@6700,4350 13450,4350 13881.69,3918.31 13881.69,941.9 13363.58,423.79 J4A.9@13363.58,219.09
  Bottom Layer w15: JP1A.63@1700,4350 1950,4350 2000,4400 3150,4400 JP1B.63@3200,4350 3450,4350 3500,4400 5150,4400 JP1C.63@5200,4350 5450,4350 5500,4400 6650,4400 JP1D.63@6700,4350
NetJ4B_1: J4B.1 JP1E.49 JP1F.49 JP1G.49 JP1H.49 | length 15428.7
  Signal Layer 1 w15: J4B.1@1418.11,5319.09 1418.11,5068.11 900,4550 900,2050 950,2000 JP1H.49@7700,2000
  Bottom Layer w15: JP1H.49@7700,2000 7750,1950 8900,1950 8950,2000 JP1G.49@9200,2000 9250,1950 10900,1950 10950,2000 JP1F.49@11200,2000 11250,1950 12400,1950 12450,2000 JP1E.49@12700,2000
NetJ4B_2: J4B.2 JP1E.53 JP1F.53 JP1G.53 JP1H.53 | length 15673.9
  Signal Layer 1 w15: J4B.2@1309.06,5319.09 1309.06,5113.28 790.94,4595.17 790.94,1959.06 950,1800 JP1H.53@7700,1800
  Bottom Layer w15: JP1H.53@7700,1800 7750,1750 8900,1750 8950,1800 JP1G.53@9200,1800 9250,1750 10900,1750 10950,1800 JP1F.53@11200,1800 11250,1750 12400,1750 12450,1800 JP1E.53@12700,1800
NetJ4B_3: J4B.3 JP1E.57 JP1F.57 JP1G.57 JP1H.57 | length 15919
  Signal Layer 1 w15: J4B.3@1200,5319.09 1200,5158.45 681.89,4640.34 681.89,1868.11 950,1600 JP1H.57@7700,1600
  Bottom Layer w15: JP1H.57@7700,1600 7750,1550 8900,1550 8950,1600 JP1G.57@9200,1600 9250,1550 10900,1550 10950,1600 JP1F.57@11200,1600 11250,1550 12400,1550 12450,1600 JP1E.57@12700,1600
NetJ4B_4: J4B.4 JP1E.61 JP1F.61 JP1G.61 JP1H.61 | length 16164.2
  Signal Layer 1 w15: J4B.4@1090.94,5319.09 1090.94,5203.63 572.83,4685.52 572.83,1777.17 950,1400 JP1H.61@7700,1400
  Bottom Layer w15: JP1H.61@7700,1400 7750,1350 8900,1350 8950,1400 JP1G.61@9200,1400 9250,1350 10900,1350 10950,1400 JP1F.61@11200,1400 11250,1350 12400,1350 12450,1400 JP1E.61@12700,1400
NetJ4B_6: J4B.6 JP1E.51 JP1F.51 JP1G.51 JP1H.51 | length 15663.1
  Signal Layer 1 w15: J4B.6@1363.58,5430.91 1363.58,5090.7 845.47,4572.59 845.47,2004.53 950,1900 JP1H.51@7700,1900
  Bottom Layer w15: JP1H.51@7700,1900 7750,1850 8900,1850 8950,1900 JP1G.51@9200,1900 9250,1850 10900,1850 10950,1900 JP1F.51@11200,1900 11250,1850 12400,1850 12450,1900 JP1E.51@12700,1900
NetJ4B_7: J4B.7 JP1E.55 JP1F.55 JP1G.55 JP1H.55 | length 15908.2
  Signal Layer 1 w15: J4B.7@1254.53,5430.91 1254.53,5135.87 736.42,4617.76 736.42,1913.58 950,1700 JP1H.55@7700,1700
  Bottom Layer w15: JP1H.55@7700,1700 7750,1650 8900,1650 8950,1700 JP1G.55@9200,1700 9250,1650 10900,1650 10950,1700 JP1F.55@11200,1700 11250,1650 12400,1650 12450,1700 JP1E.55@12700,1700
NetJ4B_8: J4B.8 JP1E.59 JP1F.59 JP1G.59 JP1H.59 | length 16153.4
  Signal Layer 1 w15: J4B.8@1145.47,5430.91 1145.47,5181.04 627.36,4662.93 627.36,1822.64 950,1500 JP1H.59@7700,1500
  Bottom Layer w15: JP1H.59@7700,1500 7750,1450 8900,1450 8950,1500 JP1G.59@9200,1500 9250,1450 10900,1450 10950,1500 JP1F.59@11200,1500 11250,1450 12400,1450 12450,1500 JP1E.59@12700,1500
NetJ4B_9: J4B.9 JP1E.63 JP1F.63 JP1G.63 JP1H.63 | length 16398.6
  Signal Layer 1 w15: J4B.9@1036.42,5430.91 1036.42,5226.21 518.31,4708.1 518.31,1731.69 950,1300 JP1H.63@7700,1300
  Bottom Layer w15: JP1H.63@7700,1300 7750,1250 8900,1250 8950,1300 JP1G.63@9200,1300 9250,1250 10900,1250 10950,1300 JP1F.63@11200,1300 11250,1250 12400,1250 12450,1300 JP1E.63@12700,1300
NetJP1A_2: JP1A.2 JP1A.18 JP1A.34 JP1A.50 P1A.1 | length 4028
  Top Layer w15: P1A.1@1418.11,330.91 v1(1418.11,1250) v1(1418.11,2050) v1(1418.11,2850) 1418.11,3618.11 1450,3650 JP1A.50@1600,3650
  Bottom Layer w15: v1(1418.11,1250) JP1A.2@1600,1250 ; v1(1418.11,2050) JP1A.18@1600,2050 ; v1(1418.11,2850) JP1A.34@1600,2850
NetJP1A_4: JP1A.4 JP1A.20 JP1A.36 JP1A.52 P1A.6 | length 4455.2
  Top Layer w15: P1A.6@1363.58,219.09 v1(1363.58,1350) v1(1363.58,2150) v1(1363.58,2950) 1363.58,3713.58 1400,3750 JP1A.52@1600,3750
  Bottom Layer w15: v1(1363.58,1350) JP1A.4@1600,1350 ; v1(1363.58,2150) JP1A.20@1600,2150 ; v1(1363.58,2950) JP1A.36@1600,2950
NetJP1A_6: JP1A.6 JP1A.22 JP1A.38 JP1A.54 P1A.2 | length 4653.6
  Top Layer w15: P1A.2@1309.06,330.91 v1(1309.06,1450) v1(1309.06,2250) v1(1309.06,3050) 1309.06,3800 1359.06,3850 JP1A.54@1600,3850
  Bottom Layer w15: v1(1309.06,1450) JP1A.6@1600,1450 ; v1(1309.06,2250) JP1A.22@1600,2250 ; v1(1309.06,3050) JP1A.38@1600,3050
NetJP1A_8: JP1A.8 JP1A.24 JP1A.40 JP1A.56 P1A.7 | length 5083.5
  Top Layer w15: P1A.7@1254.53,219.09 v1(1254.53,1550) v1(1254.53,2350) v1(1254.53,3150) 1254.53,3900 1304.53,3950 JP1A.56@1600,3950
  Bottom Layer w15: v1(1254.53,1550) JP1A.8@1600,1550 ; v1(1254.53,2350) JP1A.24@1600,2350 ; v1(1254.53,3150) JP1A.40@1600,3150
NetJP1A_10: JP1A.10 JP1A.26 JP1A.42 JP1A.58 P1A.3 | length 5289.8
  Top Layer w15: P1A.3@1200,330.91 v1(1200,1650) v1(1200,2450) v1(1200,3250) 1200,4000 1250,4050 JP1A.58@1600,4050
  Bottom Layer w15: v1(1200,1650) JP1A.10@1600,1650 ; v1(1200,2450) JP1A.26@1600,2450 ; v1(1200,3250) JP1A.42@1600,3250
NetJP1A_12: JP1A.12 JP1A.28 JP1A.44 JP1A.60 P1A.8 | length 5731.7
  Top Layer w15: P1A.8@1145.47,219.09 v1(1145.47,1750) v1(1145.47,2550) v1(1145.47,3350) 1145.47,4120.47 1175,4150 JP1A.60@1600,4150
  Bottom Layer w15: v1(1145.47,1750) JP1A.12@1600,1750 ; v1(1145.47,2550) JP1A.28@1600,2550 ; v1(1145.47,3350) JP1A.44@1600,3350
NetJP1A_14: JP1A.14 JP1A.30 JP1A.46 JP1A.62 P1A.4 | length 5935.4
  Top Layer w15: P1A.4@1090.94,330.91 v1(1090.94,1850) v1(1090.94,2650) v1(1090.94,3450) 1090.94,4215.94 1125,4250 JP1A.62@1600,4250
  Bottom Layer w15: v1(1090.94,1850) JP1A.14@1600,1850 ; v1(1090.94,2650) JP1A.30@1600,2650 ; v1(1090.94,3450) JP1A.46@1600,3450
